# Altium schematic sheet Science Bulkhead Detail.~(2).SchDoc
size B; Organization: Monterey Bay Aquarium Research Institute; Address1: 7700 Sandholdt Rd; Address2: Moss Landing, CA 95039-9644; CompanyName: MBARI
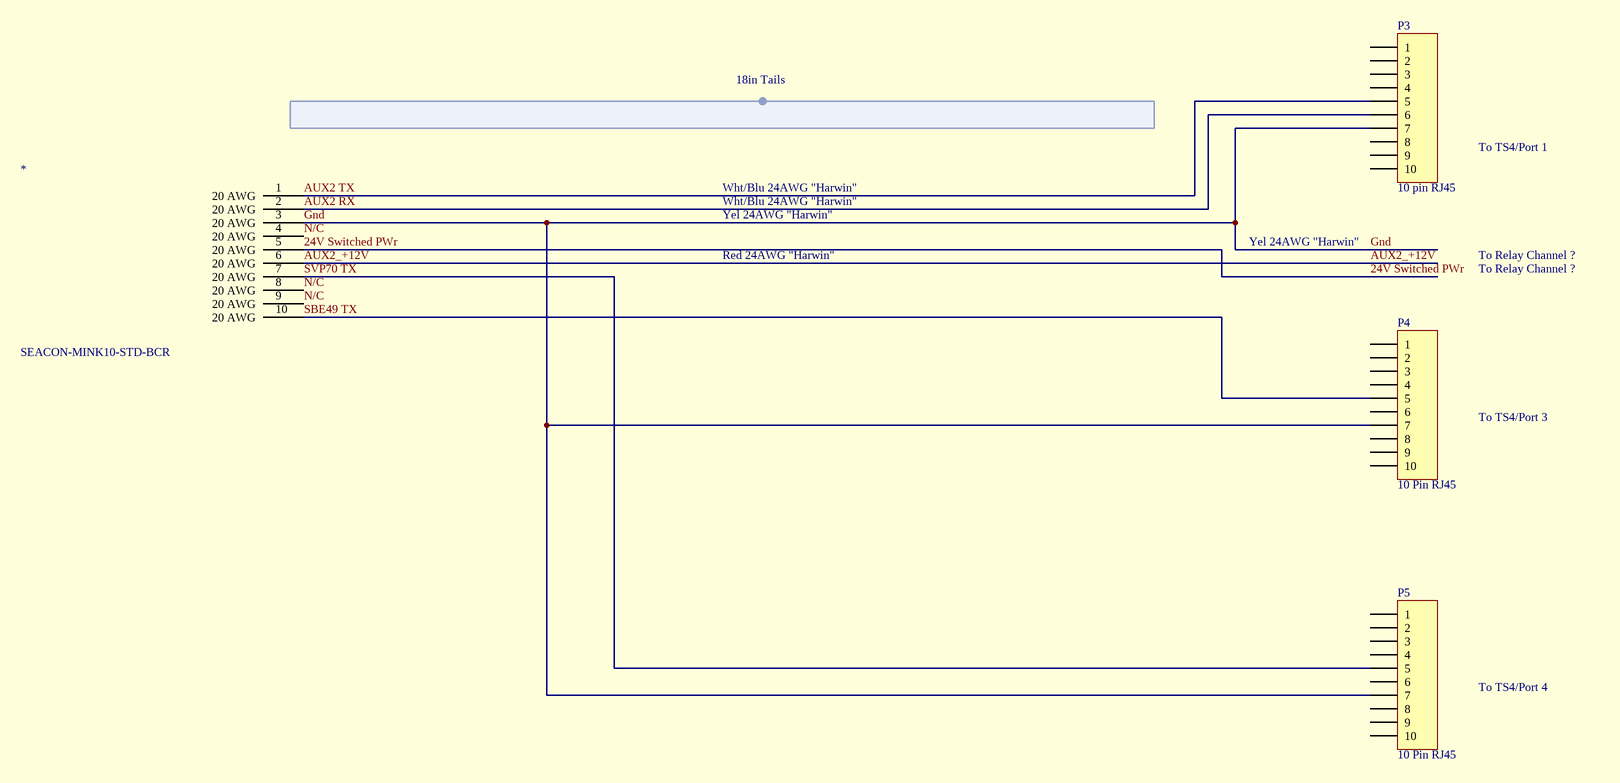
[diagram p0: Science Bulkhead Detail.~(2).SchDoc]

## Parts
*  SEACON-MINK10-STD-BCR
P3  10 pin RJ45  [HDR1X10]
P4  10 Pin RJ45  [HDR1X10]
P5  10 Pin RJ45  [HDR1X10]

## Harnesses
18in Tails: 

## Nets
24V Switched PWr: *.5(20_AWG)
AUX2 RX: *.2(20_AWG) P3.6
AUX2 TX: *.1(20_AWG) P3.5
AUX2_+12V: *.6(20_AWG)
Gnd: *.3(20_AWG) P3.7 P4.7 P5.7
N/C: *.4(20_AWG) *.8(20_AWG) *.9(20_AWG)
SBE49 TX: *.10(20_AWG) P4.5
SVP70 TX: *.7(20_AWG) P5.5

Not connected (* = marked no-connect by the designer): P3 1 2 3 4 8 9 10; P4 1 2 3 4 6 8 9 10; P5 1 2 3 4 6 8 9 10

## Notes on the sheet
- To TS4/Port 1
- Wht/Blu 24AWG "Harwin"
- Yel 24AWG "Harwin"
- Red 24AWG "Harwin"
- To Relay Channel ?
- To TS4/Port 3
- To TS4/Port 4

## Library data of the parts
* = SEACON-MINK10-STD-BCR: Seacon MINK10 BCR Standard Length
P3-P5 = Header 10: Header, 10-Pin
